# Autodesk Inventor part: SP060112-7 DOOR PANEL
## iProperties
Created: 2012-06
Part Number: SP060112-7 DOOR PANEL
Material: Polycarbonate, Clear
Document SubType Name: Modeling
Designer: Administrator
Mass: 4785.53 g
Surface Area: 14462.1 cm^2
Volume: 3987.94 cm^3
Density: 1.2 g/cm^3
Author: Administrator
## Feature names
1. Extrusion1
